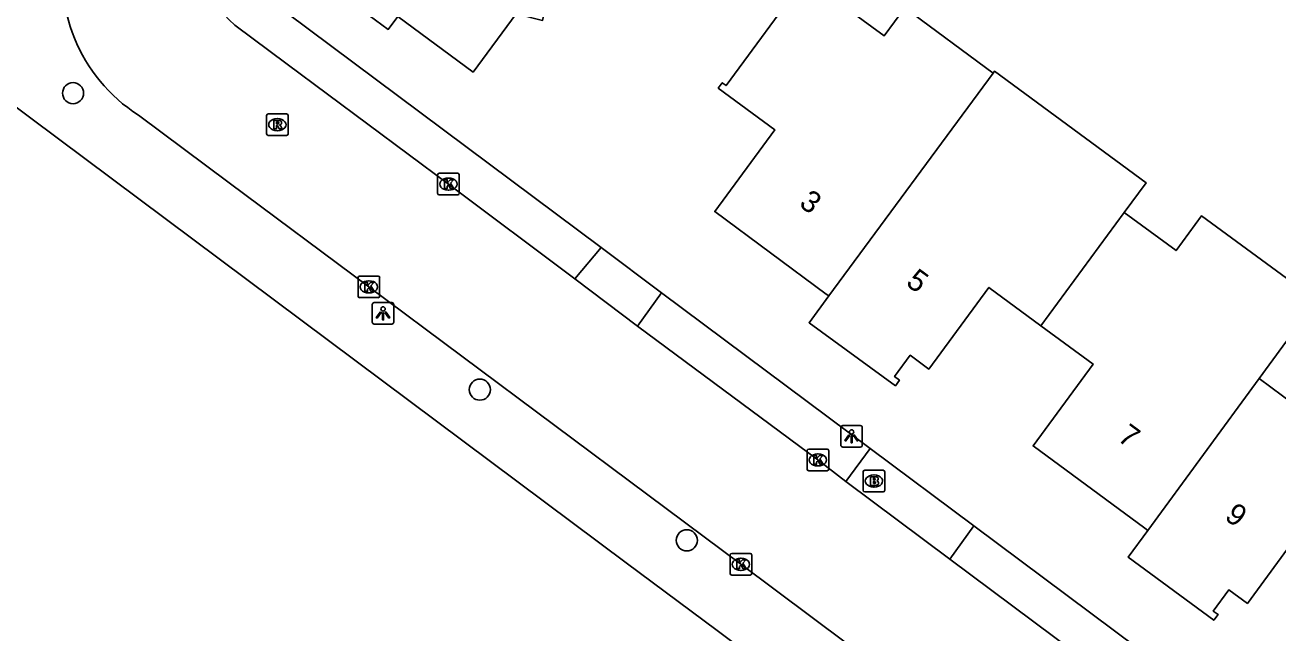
# Model space of a CAD drawing. Extents: x 163268 to 164360, y 381529 to 382285.
# Drawn here: x 163848.4 to 163906.4, y 382092 to 382120.2 of the extents above; entities that cross this region are included whole.
import ezdxf

# ---------------------------------------------------------------- set-up
doc = ezdxf.new("R2010")
doc.units = 0
for name, color, linetype in [('IMGEO_Boom', 7, 'Continuous'), ('IMGEO_Brandkraan', 7, 'Continuous'), ('IMGEO_Kolk', 7, 'Continuous'), ('IMGEO_Lichtpunt', 7, 'Continuous'), ('IMGEO_Pand', 7, 'Continuous'), ('IMGEO_Pand_nummerreeks', 7, 'Continuous'), ('IMGEO_Parkeervlak_open', 7, 'Continuous'), ('IMGEO_Rijbaan_lokaal_open', 7, 'Continuous'), ('IMGEO_Rioolput', 7, 'Continuous'), ('IMGEO_Voetpad_halfverhard', 7, 'Continuous'), ('IMGEO_Voetpad_open', 7, 'Continuous')]:
    doc.layers.add(name, color=color, linetype=linetype)

msp = doc.modelspace()

# ---------------------------------------------------------------- linework, layer by layer
at = {"layer": 'IMGEO_Boom'}
for centre in [(163850.584, 382117.007), (163869.412, 382103.285), (163878.992, 382096.308)]:
    msp.add_circle(centre, 0.489, dxfattribs=at)
at = {"layer": 'IMGEO_Brandkraan'}
for p, q in [((163887.154, 382098.628), (163887.154, 382099.48)), ((163887.229, 382099.554), (163888.081, 382099.554)), ((163888.155, 382099.48), (163888.155, 382098.628)), ((163887.642, 382099.334), (163887.667, 382099.334)), ((163888.081, 382098.554), (163887.229, 382098.554)), ((163887.665, 382098.774), (163887.64, 382098.774))]:
    msp.add_line(p, q, dxfattribs=at)
for points in [[(163887.154, 382098.628), (163887.154, 382099.48)], [(163887.229, 382099.554), (163888.081, 382099.554)], [(163888.155, 382099.48), (163888.155, 382098.628)], [(163887.502, 382099.254), (163887.502, 382098.854), (163887.715, 382098.854)], [(163887.733, 382099.254), (163887.502, 382099.254)], [(163887.681, 382099.173), (163887.627, 382099.173), (163887.627, 382099.097)], [(163887.627, 382099.097), (163887.68, 382099.097)], [(163887.689, 382099.021), (163887.627, 382099.021), (163887.627, 382098.94)], [(163887.627, 382098.94), (163887.689, 382098.94)], [(163888.081, 382098.554), (163887.229, 382098.554)]]:
    msp.add_lwpolyline(points, dxfattribs=at)
for centre, radius, start, end in [((163887.231, 382099.478), 0.0765, 91.55205, 178.44795), ((163887.231, 382099.478), 0.0765, 91.55205, 178.44795), ((163888.079, 382099.478), 0.0765, 1.55205, 88.44795), ((163888.079, 382099.478), 0.0765, 1.55205, 88.44795), ((163887.682, 382099.135), 0.0379, 267.82845, 90.93552), ((163887.69, 382098.98), 0.0404, 269.87594, 90.50774), ((163887.721, 382099.105), 0.251, 268.66757, 293.53466), ((163887.737, 382099.109), 0.145, 59.4692, 91.53667), ((163887.762, 382099.156), 0.0922, 285.51372, 58.15012), ((163887.767, 382098.964), 0.105, 301.31148, 78.98903), ((163887.231, 382098.63), 0.0765, 181.55205, 268.44795), ((163887.231, 382098.63), 0.0765, 181.55205, 268.44795), ((163888.079, 382098.63), 0.0765, 271.55205, 358.44795), ((163888.079, 382098.63), 0.0765, 271.55205, 358.44795)]:
    msp.add_arc(centre, radius, start, end, dxfattribs=at)
for centre, major_axis, ratio, start_param, end_param in [((163887.641, 382099.054), (-0.387, 0.002), 0.722429, 4.712389, 7.853982), ((163887.666, 382099.054), (-0.39, 0.002), 0.717154, 1.570796, 4.712389)]:
    msp.add_ellipse(centre, major_axis=major_axis, ratio=ratio, start_param=start_param, end_param=end_param, dxfattribs=at)
at = {"layer": 'IMGEO_Kolk'}
for p, q in [((163867.534, 382113.298), (163868.386, 382113.298)), ((163867.459, 382112.372), (163867.459, 382113.224)), ((163867.947, 382113.078), (163867.972, 382113.078)), ((163868.46, 382113.224), (163868.46, 382112.372)), ((163868.386, 382112.298), (163867.534, 382112.298)), ((163867.97, 382112.518), (163867.945, 382112.518)), ((163863.774, 382107.616), (163863.774, 382108.468)), ((163863.849, 382108.542), (163864.701, 382108.542)), ((163864.262, 382108.322), (163864.287, 382108.322)), ((163864.775, 382108.468), (163864.775, 382107.616)), ((163864.701, 382107.542), (163863.849, 382107.542)), ((163864.285, 382107.762), (163864.26, 382107.762)), ((163884.633, 382100.53), (163885.485, 382100.53)), ((163884.558, 382099.604), (163884.558, 382100.456)), ((163885.046, 382100.31), (163885.071, 382100.31)), ((163885.559, 382100.456), (163885.559, 382099.604)), ((163885.485, 382099.53), (163884.633, 382099.53)), ((163885.069, 382099.75), (163885.044, 382099.75)), ((163880.994, 382094.773), (163880.994, 382095.625)), ((163881.069, 382095.699), (163881.921, 382095.699)), ((163881.482, 382095.479), (163881.507, 382095.479)), ((163881.995, 382095.625), (163881.995, 382094.773)), ((163881.505, 382094.919), (163881.48, 382094.919)), ((163881.921, 382094.699), (163881.069, 382094.699))]:
    msp.add_line(p, q, dxfattribs=at)
for points in [[(163867.534, 382113.298), (163868.386, 382113.298)], [(163867.459, 382112.372), (163867.459, 382113.224)], [(163867.78, 382112.998), (163867.903, 382112.998), (163867.903, 382112.847), (163868.033, 382112.998), (163868.197, 382112.998), (163868.051, 382112.847), (163868.204, 382112.598), (163868.052, 382112.598), (163867.967, 382112.762), (163867.903, 382112.695), (163867.903, 382112.598), (163867.78, 382112.598), (163867.78, 382112.998)], [(163868.46, 382113.224), (163868.46, 382112.372)], [(163868.386, 382112.298), (163867.534, 382112.298)], [(163863.774, 382107.616), (163863.774, 382108.468)], [(163863.849, 382108.542), (163864.701, 382108.542)], [(163864.095, 382108.242), (163864.218, 382108.242), (163864.218, 382108.091), (163864.348, 382108.242), (163864.512, 382108.242), (163864.366, 382108.091), (163864.519, 382107.842), (163864.367, 382107.842), (163864.282, 382108.006), (163864.218, 382107.939), (163864.218, 382107.842), (163864.095, 382107.842), (163864.095, 382108.242)], [(163864.775, 382108.468), (163864.775, 382107.616)], [(163864.701, 382107.542), (163863.849, 382107.542)], [(163884.633, 382100.53), (163885.485, 382100.53)], [(163884.558, 382099.604), (163884.558, 382100.456)], [(163884.879, 382100.23), (163885.002, 382100.23), (163885.002, 382100.079), (163885.132, 382100.23), (163885.296, 382100.23), (163885.15, 382100.079), (163885.303, 382099.83), (163885.151, 382099.83), (163885.066, 382099.994), (163885.002, 382099.927), (163885.002, 382099.83), (163884.879, 382099.83), (163884.879, 382100.23)], [(163885.559, 382100.456), (163885.559, 382099.604)], [(163885.485, 382099.53), (163884.633, 382099.53)], [(163880.994, 382094.773), (163880.994, 382095.625)], [(163881.069, 382095.699), (163881.921, 382095.699)], [(163881.315, 382095.399), (163881.438, 382095.399), (163881.438, 382095.248), (163881.568, 382095.399), (163881.732, 382095.399), (163881.586, 382095.248), (163881.739, 382094.999), (163881.587, 382094.999), (163881.502, 382095.163), (163881.438, 382095.096), (163881.438, 382094.999), (163881.315, 382094.999), (163881.315, 382095.399)], [(163881.995, 382095.625), (163881.995, 382094.773)], [(163881.921, 382094.699), (163881.069, 382094.699)]]:
    msp.add_lwpolyline(points, dxfattribs=at)
for centre, start, end in [((163867.536, 382113.222), 91.55205, 178.44795), ((163867.536, 382113.222), 91.55205, 178.44795), ((163868.384, 382113.222), 1.55205, 88.44795), ((163868.384, 382113.222), 1.55205, 88.44795), ((163867.536, 382112.374), 181.55205, 268.44795), ((163867.536, 382112.374), 181.55205, 268.44795), ((163868.384, 382112.374), 271.55205, 358.44795), ((163868.384, 382112.374), 271.55205, 358.44795), ((163863.851, 382108.466), 91.55205, 178.44795), ((163863.851, 382108.466), 91.55205, 178.44795), ((163864.699, 382108.466), 1.55205, 88.44795), ((163864.699, 382108.466), 1.55205, 88.44795), ((163863.851, 382107.618), 181.55205, 268.44795), ((163863.851, 382107.618), 181.55205, 268.44795), ((163864.699, 382107.618), 271.55205, 358.44795), ((163864.699, 382107.618), 271.55205, 358.44795), ((163884.635, 382100.454), 91.55205, 178.44795), ((163884.635, 382100.454), 91.55205, 178.44795), ((163885.483, 382100.454), 1.55205, 88.44795), ((163885.483, 382100.454), 1.55205, 88.44795), ((163884.635, 382099.606), 181.55205, 268.44795), ((163884.635, 382099.606), 181.55205, 268.44795), ((163885.483, 382099.606), 271.55205, 358.44795), ((163885.483, 382099.606), 271.55205, 358.44795), ((163881.071, 382095.623), 91.55205, 178.44795), ((163881.071, 382095.623), 91.55205, 178.44795), ((163881.919, 382095.623), 1.55205, 88.44795), ((163881.919, 382095.623), 1.55205, 88.44795), ((163881.071, 382094.775), 181.55205, 268.44795), ((163881.071, 382094.775), 181.55205, 268.44795), ((163881.919, 382094.775), 271.55205, 358.44795), ((163881.919, 382094.775), 271.55205, 358.44795)]:
    msp.add_arc(centre, 0.0765, start, end, dxfattribs=at)
for centre, major_axis, ratio, start_param, end_param in [((163867.946, 382112.798), (-0.387, 0.002), 0.722429, 4.712389, 7.853982), ((163867.971, 382112.798), (-0.39, 0.002), 0.717154, 1.570796, 4.712389), ((163864.261, 382108.042), (-0.387, 0.002), 0.722429, 4.712389, 7.853982), ((163864.286, 382108.042), (-0.39, 0.002), 0.717154, 1.570796, 4.712389), ((163885.045, 382100.03), (-0.387, 0.002), 0.722429, 4.712389, 7.853982), ((163885.07, 382100.03), (-0.39, 0.002), 0.717154, 1.570796, 4.712389), ((163881.481, 382095.199), (-0.387, 0.002), 0.722429, 4.712389, 7.853982), ((163881.506, 382095.199), (-0.39, 0.002), 0.717154, 1.570796, 4.712389)]:
    msp.add_ellipse(centre, major_axis=major_axis, ratio=ratio, start_param=start_param, end_param=end_param, dxfattribs=at)
at = {"layer": 'IMGEO_Lichtpunt'}
for p, q in [((163864.433, 382107.221), (163864.433, 382106.414)), ((163864.433, 382107.221), (163864.433, 382106.414)), ((163865.335, 382107.316), (163864.527, 382107.316)), ((163865.335, 382107.316), (163864.527, 382107.316)), ((163865.429, 382106.414), (163865.429, 382107.221)), ((163865.429, 382106.414), (163865.429, 382107.221)), ((163864.527, 382106.32), (163865.335, 382106.32)), ((163864.527, 382106.32), (163865.335, 382106.32)), ((163886.12, 382101.529), (163886.12, 382100.722)), ((163886.12, 382101.529), (163886.12, 382100.722)), ((163887.022, 382101.624), (163886.214, 382101.624)), ((163887.022, 382101.624), (163886.214, 382101.624)), ((163887.116, 382100.722), (163887.116, 382101.529)), ((163887.116, 382100.722), (163887.116, 382101.529)), ((163886.214, 382100.628), (163887.022, 382100.628)), ((163886.214, 382100.628), (163887.022, 382100.628))]:
    msp.add_line(p, q, dxfattribs=at)
for points in [[(163864.807, 382106.885), (163864.846, 382106.857), (163864.658, 382106.595), (163864.62, 382106.622), (163864.807, 382106.885)], [(163864.909, 382106.837), (163864.956, 382106.837), (163864.956, 382106.515), (163864.909, 382106.515), (163864.909, 382106.837)], [(163865.019, 382106.857), (163865.057, 382106.884), (163865.244, 382106.622), (163865.205, 382106.594), (163865.019, 382106.857)], [(163886.494, 382101.193), (163886.533, 382101.165), (163886.345, 382100.903), (163886.307, 382100.93), (163886.494, 382101.193)], [(163886.596, 382101.145), (163886.643, 382101.145), (163886.643, 382100.823), (163886.596, 382100.823), (163886.596, 382101.145)], [(163886.706, 382101.165), (163886.744, 382101.192), (163886.931, 382100.93), (163886.892, 382100.902), (163886.706, 382101.165)]]:
    msp.add_lwpolyline(points, dxfattribs=at)
for centre in [(163864.932, 382107.019), (163886.619, 382101.327)]:
    msp.add_circle(centre, 0.0994, dxfattribs=at)
for centre, start, end in [((163864.527, 382107.221), 90, 180), ((163864.527, 382107.221), 90, 180), ((163865.335, 382107.221), 0, 90), ((163865.335, 382107.221), 0, 90), ((163864.527, 382106.414), 180, 270), ((163864.527, 382106.414), 180, 270), ((163865.335, 382106.414), 270, 0), ((163865.335, 382106.414), 270, 360), ((163886.214, 382101.529), 90, 180), ((163886.214, 382101.529), 90, 180), ((163887.022, 382101.529), 0, 90), ((163887.022, 382101.529), 0, 90), ((163886.214, 382100.722), 180, 270), ((163886.214, 382100.722), 180, 270), ((163887.022, 382100.722), 270, 0), ((163887.022, 382100.722), 270, 360)]:
    msp.add_arc(centre, 0.0946, start, end, dxfattribs=at)
at = {"layer": 'IMGEO_Pand'}
for points in [[(163871.824, 382131.062), (163874.562, 382130.386), (163873.516, 382126.153), (163873.732, 382126.101), (163872.317, 382120.372), (163871.086, 382120.676), (163869.103, 382117.987), (163865.614, 382120.56), (163865.173, 382119.961), (163862.235, 382122.128), (163863.621, 382127.795), (163863.928, 382127.724), (163863.852, 382127.465), (163865.033, 382127.157), (163865.308, 382128.212), (163867.273, 382127.699), (163868.378, 382131.893), (163868.658, 382131.847)], [(163885.564, 382107.622), (163885.443, 382107.711), (163880.284, 382111.528), (163883.065, 382115.317), (163880.447, 382117.242), (163880.631, 382117.492), (163880.809, 382117.362), (163884.47, 382122.341), (163888.122, 382119.656), (163889.079, 382120.954), (163893.169, 382117.939)], [(163893.169, 382117.939), (163885.564, 382107.622)], [(163893.169, 382117.939), (163893.236, 382118.029), (163900.255, 382112.855), (163899.24, 382111.484)], [(163895.386, 382106.241), (163899.24, 382111.484)], [(163899.24, 382111.484), (163901.637, 382109.721), (163902.823, 382111.333), (163908.144, 382107.42), (163905.478, 382103.795)], [(163895.386, 382106.241), (163892.973, 382108.017), (163890.191, 382104.236), (163889.337, 382104.874), (163888.611, 382103.887), (163888.836, 382103.721), (163888.649, 382103.462), (163884.65, 382106.382), (163885.564, 382107.622)], [(163905.478, 382103.795), (163908.193, 382101.799), (163909.674, 382103.814), (163910.661, 382103.088), (163913.061, 382106.352), (163916.385, 382103.908)], [(163900.327, 382096.769), (163900.199, 382096.864), (163895.017, 382100.682), (163897.8, 382104.464), (163895.386, 382106.241)], [(163900.327, 382096.769), (163905.478, 382103.795)], [(163910.126, 382095.393), (163907.717, 382097.173), (163904.941, 382093.391), (163904.087, 382094.023), (163903.361, 382093.037), (163903.58, 382092.876), (163903.386, 382092.611), (163899.42, 382095.532), (163900.327, 382096.769)]]:
    msp.add_lwpolyline(points, dxfattribs=at)
at = {"layer": 'IMGEO_Parkeervlak_open'}
for points in [[(163877.815, 382107.76), (163887.481, 382100.555)], [(163892.281, 382096.981), (163902.018, 382089.71)]]:
    msp.add_lwpolyline(points, dxfattribs=at)
at = {"layer": 'IMGEO_Rijbaan_lokaal_open'}
for points in [[(163858.075, 382120.161), (163860.486, 382118.358), (163867.96, 382112.796), (163873.803, 382108.419)], [(163931.652, 382057.738), (163929.876, 382059.068), (163916.68, 382068.927), (163899.475, 382081.765), (163881.495, 382095.2), (163864.276, 382108.044), (163857.807, 382112.86), (163853.607, 382115.993)], [(163876.717, 382106.223), (163873.803, 382108.419)], [(163886.36, 382099.036), (163885.057, 382100.029), (163876.717, 382106.223)], [(163891.163, 382095.44), (163886.36, 382099.036)], [(163891.163, 382095.44), (163900.884, 382088.189)]]:
    msp.add_lwpolyline(points, dxfattribs=at)
for centre, radius, start, end in [((163861.41, 382124.04), 5.116, 167.22023, 229.31318), ((163857.697, 382122.392), 7.595, 166.46383, 237.419)]:
    msp.add_arc(centre, radius, start, end, dxfattribs=at)
at = {"layer": 'IMGEO_Rioolput'}
for p, q in [((163859.539, 382115.124), (163859.539, 382115.976)), ((163859.614, 382116.05), (163860.466, 382116.05)), ((163860.027, 382115.83), (163860.052, 382115.83)), ((163860.54, 382115.976), (163860.54, 382115.124)), ((163860.466, 382115.05), (163859.614, 382115.05)), ((163860.05, 382115.27), (163860.025, 382115.27))]:
    msp.add_line(p, q, dxfattribs=at)
for points in [[(163859.539, 382115.124), (163859.539, 382115.976)], [(163859.614, 382116.05), (163860.466, 382116.05)], [(163860.128, 382115.748), (163859.876, 382115.75), (163859.876, 382115.35)], [(163860.054, 382115.669), (163860, 382115.669), (163860, 382115.588)], [(163860.54, 382115.976), (163860.54, 382115.124)], [(163860.466, 382115.05), (163859.614, 382115.05)], [(163859.876, 382115.35), (163860, 382115.35), (163860, 382115.512), (163860.011, 382115.512)], [(163860, 382115.588), (163860.052, 382115.588)], [(163860.058, 382115.483), (163860.129, 382115.35), (163860.269, 382115.35), (163860.204, 382115.476)]]:
    msp.add_lwpolyline(points, dxfattribs=at)
for centre, radius, start, end in [((163859.616, 382115.974), 0.0765, 91.55205, 178.44795), ((163859.616, 382115.974), 0.0765, 91.55205, 178.44795), ((163860.06, 382115.573), 0.0964, 77.00612, 93.18647), ((163860.074, 382115.63), 0.0378, 276.66336, 79.67722), ((163860.127, 382115.638), 0.109, 350.36119, 89.41601), ((163860.125, 382115.638), 0.112, 277.58423, 350.98172), ((163860.464, 382115.974), 0.0765, 1.55205, 88.44795), ((163860.464, 382115.974), 0.0765, 1.55205, 88.44795), ((163859.616, 382115.126), 0.0765, 181.55205, 268.44795), ((163859.616, 382115.126), 0.0765, 181.55205, 268.44795), ((163860.01, 382115.459), 0.0533, 26.02933, 88.69889), ((163860.036, 382115.777), 0.19, 274.7715, 282.96867), ((163860.109, 382115.423), 0.108, 29.51342, 73.79051), ((163860.464, 382115.126), 0.0765, 271.55205, 358.44795), ((163860.464, 382115.126), 0.0765, 271.55205, 358.44795)]:
    msp.add_arc(centre, radius, start, end, dxfattribs=at)
for centre, major_axis, ratio, start_param, end_param in [((163860.026, 382115.55), (-0.387, 0.002), 0.722429, 4.712389, 7.853982), ((163860.051, 382115.55), (-0.39, 0.002), 0.717154, 1.570796, 4.712389)]:
    msp.add_ellipse(centre, major_axis=major_axis, ratio=ratio, start_param=start_param, end_param=end_param, dxfattribs=at)
at = {"layer": 'IMGEO_Voetpad_halfverhard'}
msp.add_lwpolyline([(163859.338, 382121.573), (163860.428, 382120.764), (163875.031, 382109.86)], dxfattribs=at)
at = {"layer": 'IMGEO_Voetpad_open'}
for points in [[(163844.84, 382118.673), (163876.191, 382095.274), (163880.403, 382092.13), (163921.027, 382061.786)], [(163873.803, 382108.419), (163875.031, 382109.86)], [(163875.031, 382109.86), (163877.815, 382107.76)], [(163877.815, 382107.76), (163876.717, 382106.223)], [(163887.481, 382100.555), (163886.36, 382099.036)], [(163887.481, 382100.555), (163892.281, 382096.981)], [(163892.281, 382096.981), (163891.163, 382095.44)]]:
    msp.add_lwpolyline(points, dxfattribs=at)

# ---------------------------------------------------------------- texts
at = {"layer": 'IMGEO_Pand_nummerreeks'}
for s, rotation, p in [('3', 323.50259, (163884.141, 382111.809)), ('5', 323.50259, (163889.086, 382108.151)), ('7', 323.61718, (163898.881, 382100.965)), ('9', 323.61718, (163903.838, 382097.312))]:
    msp.add_text(s, height=1, rotation=rotation, dxfattribs=at).set_placement(p)

doc.saveas('drawing.dxf')
